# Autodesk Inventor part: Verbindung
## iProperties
Created: 2005-01
Part Number: Verbindung
Material: Standard
Document SubType Name: Modeling
Designer: ap
Manufacturer: Standard
Standards Organization: Custom
Author: ap
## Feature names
1. Basis1
